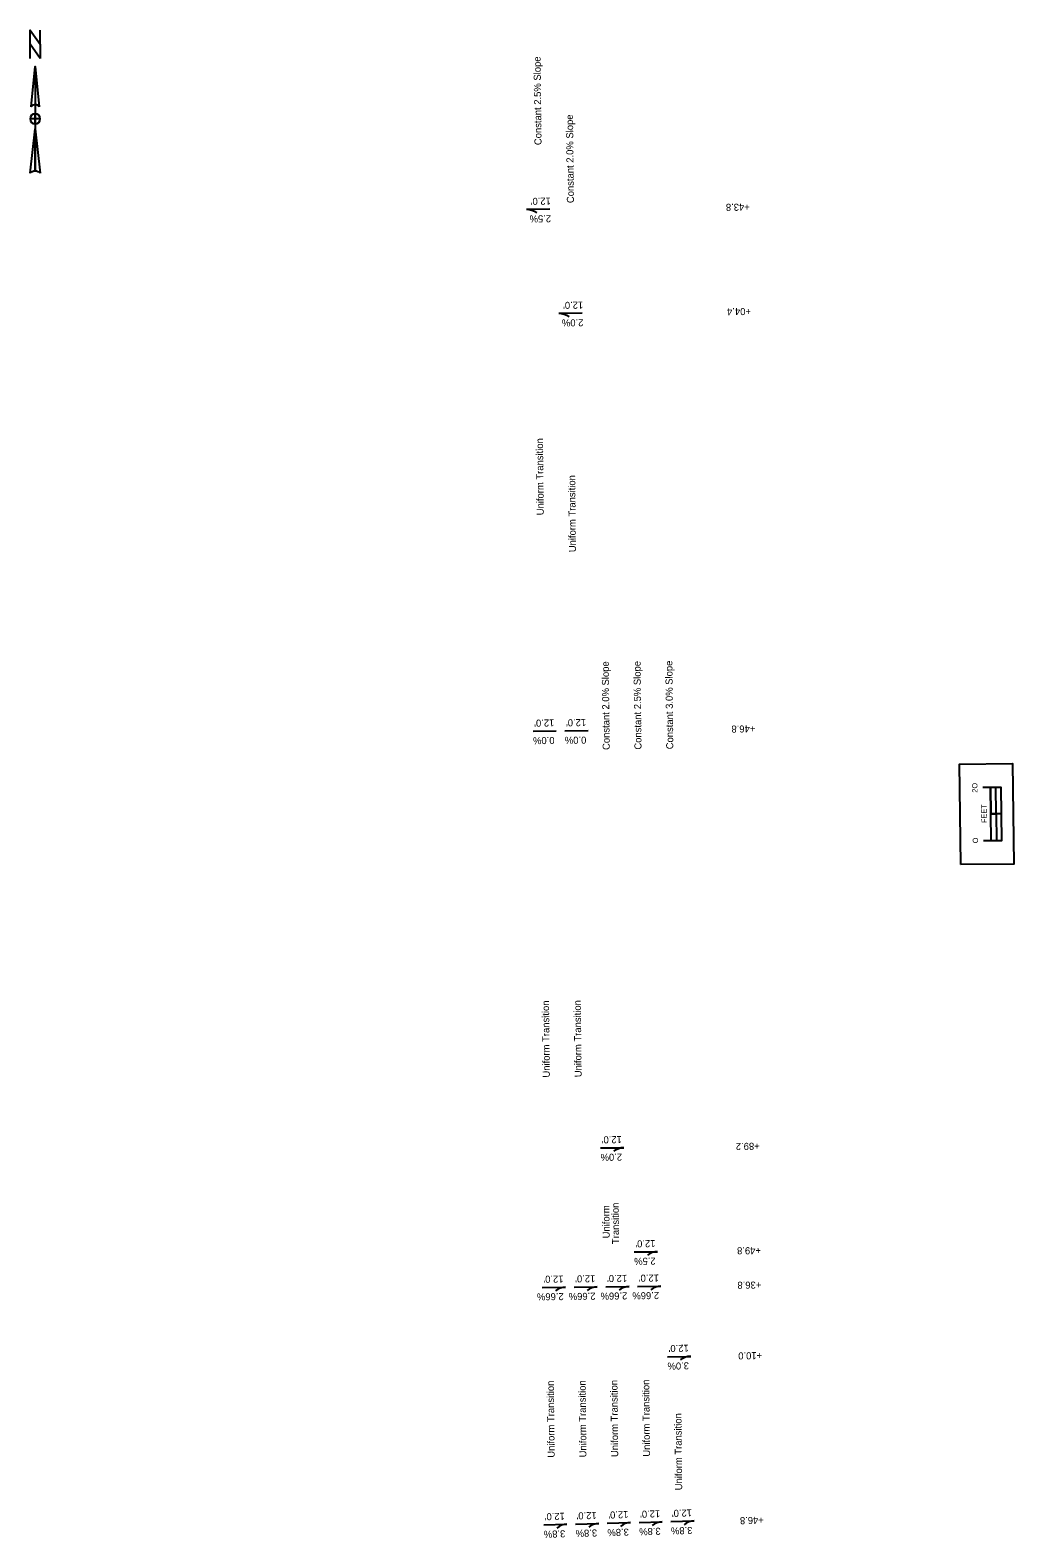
# Model space of a CAD drawing. Extents: x 20505303 to 20506906, y 7965397 to 7979025.
# Drawn here: x 20505303 to 20505674, y 7978456 to 7979025 of the extents above; entities that cross this region are included whole.
import ezdxf

# ---------------------------------------------------------------- set-up
doc = ezdxf.new("R2010")
doc.units = 0
doc.layers.add('_CIVIL_CONSTRUCTION', color=7, linetype='Continuous')
doc.layers.add('Alignment', color=7, linetype='Continuous')

msp = doc.modelspace()

# ---------------------------------------------------------------- linework, layer by layer
at = {"layer": '_CIVIL_CONSTRUCTION'}
for p, q in [((20505305.03, 7979011.59), (20505306.56, 7978996.37)), ((20505305.03, 7979011.59), (20505305.03, 7978972.03)), ((20505303.51, 7978996.37), (20505303.51, 7978996.37)), ((20505303.57, 7978996.51), (20505303.86, 7978996.83)), ((20505305.03, 7978989.91), (20505305.03, 7978989.91)), ((20505303.13, 7978971.27), (20505305.03, 7978988.01))]:
    msp.add_line(p, q, dxfattribs=at)
msp.add_lwpolyline([(20505306.94, 7979014.63), (20505303.13, 7979019.95), (20505303.13, 7979025.28), (20505306.94, 7979019.95)], close=True, dxfattribs=at)
for points in [[(20505303.13, 7979014.63), (20505303.13, 7979025.28), (20505306.94, 7979019.95), (20505306.94, 7979025.28)], [(20505303.51, 7978996.37), (20505305.03, 7979011.59), (20505305.03, 7978997.13)], [(20505305.03, 7978989.91), (20505305.03, 7978991.81), (20505303.13, 7978991.81)], [(20505306.94, 7978991.81), (20505305.03, 7978991.81), (20505305.03, 7978993.71)], [(20505305.03, 7978972.03), (20505305.03, 7978988.01), (20505306.94, 7978971.27)]]:
    msp.add_lwpolyline(points, dxfattribs=at)
for centre, radius, start, end in [((20505305.04, 7978995.23), 1.9, 90.0204, 143.1257), ((20505305.04, 7978995.23), 1.9, 36.8481, 90.0218), ((20505305.03, 7978991.81), 1.9, 90, 180), ((20505305.03, 7978991.81), 1.9, 180, 270), ((20505305.03, 7978991.81), 1.9, 0, 90), ((20505305.03, 7978991.81), 1.9, 270, 360), ((20505305.03, 7978969.28), 2.76, 89.9894, 133.619), ((20505305.03, 7978969.28), 2.76, 46.4021, 90.0006)]:
    msp.add_arc(centre, radius, start, end, dxfattribs=at)
at = {"layer": 'Alignment'}
for p, q in [((20505499.25, 7978957.65), (20505490.48, 7978957.55)), ((20505511.47, 7978918.38), (20505502.7, 7978918.28)), ((20505492.93, 7978760.57), (20505501.7, 7978760.66)), ((20505504.93, 7978760.7), (20505513.7, 7978760.79)), ((20505669.75, 7978729.37), (20505665.75, 7978729.32)), ((20505669.75, 7978729.37), (20505665.75, 7978729.32)), ((20505518.42, 7978603.23), (20505527.19, 7978603.33)), ((20505531.1, 7978563.97), (20505539.87, 7978564.06)), ((20505496.4, 7978550.59), (20505505.17, 7978550.69)), ((20505508.4, 7978550.72), (20505517.17, 7978550.82)), ((20505520.4, 7978550.85), (20505529.17, 7978550.95)), ((20505532.4, 7978550.98), (20505541.17, 7978551.07)), ((20505543.66, 7978524.42), (20505552.43, 7978524.55)), ((20505496.95, 7978460.91), (20505505.72, 7978461.14)), ((20505508.95, 7978461.22), (20505517.71, 7978461.45)), ((20505520.94, 7978461.54), (20505529.71, 7978461.77)), ((20505532.94, 7978461.86), (20505541.7, 7978462.09)), ((20505544.93, 7978462.17), (20505553.7, 7978462.41))]:
    msp.add_line(p, q, dxfattribs=at)
for points in [[(20505654.38, 7978710.19), (20505653.93, 7978748.18), (20505673.93, 7978748.42), (20505674.38, 7978710.43)], [(20505654.38, 7978710.19), (20505653.93, 7978748.18), (20505673.93, 7978748.42), (20505674.38, 7978710.43)], [(20505667.74, 7978729.35), (20505667.62, 7978739.35), (20505665.63, 7978739.32), (20505665.75, 7978729.32)], [(20505669.87, 7978719.37), (20505669.75, 7978729.37), (20505667.74, 7978729.35), (20505667.86, 7978719.35)]]:
    msp.add_lwpolyline(points, close=True, dxfattribs=at)
for points in [[(20505662.87, 7978719.29), (20505669.87, 7978719.37), (20505669.63, 7978739.37), (20505662.63, 7978739.29)], [(20505665.87, 7978719.33), (20505665.63, 7978739.32)]]:
    msp.add_lwpolyline(points, dxfattribs=at)
for centre, start, end in [((20505490.55, 7978951.39), 52.4113, 90.6143), ((20505502.76, 7978912.12), 52.4113, 90.6143), ((20505527.25, 7978597.16), 90.6143, 128.8174), ((20505539.93, 7978557.9), 90.6143, 128.8174), ((20505505.23, 7978544.53), 90.6143, 128.8174), ((20505517.23, 7978544.65), 90.6143, 128.8174), ((20505529.23, 7978544.78), 90.6143, 128.8174), ((20505541.23, 7978544.91), 90.6143, 128.8174), ((20505552.52, 7978518.39), 90.8834, 129.0864), ((20505505.88, 7978454.98), 91.5134, 129.7164), ((20505517.88, 7978455.29), 91.5134, 129.7164), ((20505529.87, 7978455.61), 91.5134, 129.7164), ((20505541.87, 7978455.93), 91.5134, 129.7164), ((20505553.86, 7978456.24), 91.5134, 129.7164)]:
    msp.add_arc(centre, 6.16, start, end, dxfattribs=at)

# ---------------------------------------------------------------- texts
for s, height, rotation, p in [('Constant 2.5% Slope', 2.664, 90.6143, (20505496.13, 7978981.88)), ('Constant 2.0% Slope', 2.664, 90.6143, (20505508.36, 7978959.99)), ("12.0'", 2.664, 180.7171, (20505499.64, 7978962.05)), ('2.5%', 2.664, 180.7171, (20505499.71, 7978955.42)), ('+43.8', 2.664, 180.6134, (20505574.7, 7978959.79)), ("12.0'", 2.664, 180.7171, (20505511.85, 7978922.78)), ('+04.4', 2.664, 180.6134, (20505575.15, 7978920.39)), ('2.0%', 2.664, 180.7171, (20505511.92, 7978916.15)), ('Uniform Transition', 2.664, 90.6143, (20505496.98, 7978842.13)), ('Uniform Transition', 2.664, 90.6143, (20505509.13, 7978828.18)), ('Constant 2.0% Slope', 2.664, 90.6143, (20505521.86, 7978753.51)), ('Constant 2.5% Slope', 2.664, 90.6143, (20505533.86, 7978753.64)), ('Constant 3.0% Slope', 2.664, 90.6143, (20505545.86, 7978753.77)), ("12.0'", 2.664, 180.7171, (20505500.95, 7978765.05)), ("12.0'", 2.664, 180.7171, (20505512.95, 7978765.18)), ('+46.8', 2.664, 180.6134, (20505576.81, 7978762.8)), ('0.0%', 2.664, 180.7171, (20505501.02, 7978758.43)), ('0.0%', 2.664, 180.7171, (20505513.02, 7978758.56)), ('2O', 2, 90.6857, (20505660.66, 7978737.39)), ('FEET', 2, 90.6857, (20505664.19, 7978725.92)), ('O', 2, 90.6857, (20505660.88, 7978718.28)), ('Uniform Transition', 2.664, 90.6143, (20505499.26, 7978629.82)), ('Uniform Transition', 2.664, 90.6143, (20505511.26, 7978629.95)), ("12.0'", 2.664, 180.7171, (20505526.44, 7978607.72)), ('+89.2', 2.664, 180.6134, (20505578.45, 7978605.21)), ('2.0%', 2.664, 180.7171, (20505526.51, 7978601.09)), ('Uniform', 2.664, 90.6143, (20505521.85, 7978569.11)), ('Transition', 2.664, 90.6143, (20505525.42, 7978566.96)), ("12.0'", 2.664, 180.7171, (20505539.12, 7978568.45)), ('2.5%', 2.664, 180.7171, (20505539.19, 7978561.83)), ('+49.8', 2.664, 180.6134, (20505578.92, 7978565.81)), ("12.0'", 2.664, 180.7171, (20505504.42, 7978555.08)), ("12.0'", 2.664, 180.7171, (20505516.42, 7978555.2)), ("12.0'", 2.664, 180.7171, (20505528.42, 7978555.33)), ("12.0'", 2.664, 180.7171, (20505540.42, 7978555.46)), ('+36.8', 2.664, 180.6134, (20505579.06, 7978552.81)), ('2.66%', 2.664, 180.7171, (20505504.49, 7978548.45)), ('2.66%', 2.664, 180.7171, (20505516.49, 7978548.58)), ('2.66%', 2.664, 180.7171, (20505528.49, 7978548.71)), ('2.66%', 2.664, 180.7171, (20505540.49, 7978548.84)), ("12.0'", 2.664, 180.9861, (20505551.66, 7978528.94)), ('3.0%', 2.664, 180.9861, (20505551.76, 7978522.31)), ('+10.0', 2.664, 180.8834, (20505579.36, 7978526.18)), ('Uniform Transition', 2.664, 90.6143, (20505501.08, 7978486.29)), ('Uniform Transition', 2.664, 90.6143, (20505513.08, 7978486.42)), ('Uniform Transition', 2.664, 90.6143, (20505525.08, 7978486.55)), ('Uniform Transition', 2.664, 90.6143, (20505537.08, 7978486.68)), ('Uniform Transition', 2.664, 90.6143, (20505549.23, 7978473.99)), ("12.0'", 2.664, 181.6161, (20505504.9, 7978465.51)), ("12.0'", 2.664, 181.6161, (20505516.9, 7978465.83)), ("12.0'", 2.664, 181.6161, (20505528.89, 7978466.15)), ("12.0'", 2.664, 181.6161, (20505540.89, 7978466.46)), ("12.0'", 2.664, 181.6161, (20505552.88, 7978466.78)), ('3.8%', 2.664, 181.6161, (20505529.07, 7978459.52)), ('3.8%', 2.664, 181.6161, (20505541.06, 7978459.84)), ('3.8%', 2.664, 181.6161, (20505553.06, 7978460.16)), ('+46.8', 2.664, 181.5134, (20505579.99, 7978464.04)), ('3.8%', 2.664, 181.6161, (20505505.07, 7978458.89)), ('3.8%', 2.664, 181.6161, (20505517.07, 7978459.21))]:
    msp.add_text(s, height=height, rotation=rotation, dxfattribs=at).set_placement(p)

doc.saveas('drawing.dxf')
